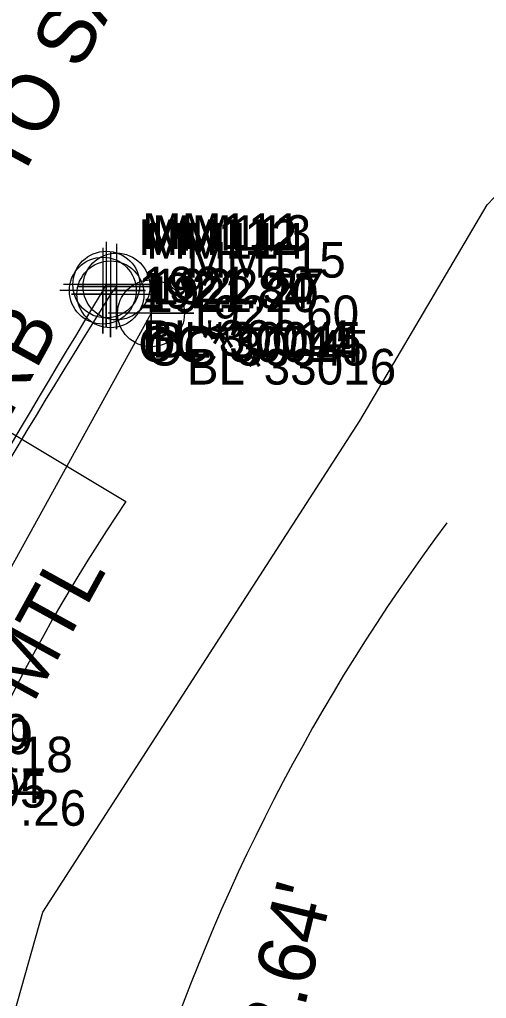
# Model space of a CAD drawing. Extents: x 1004514 to 1005247, y 553695 to 554706.
# Drawn here: x 1005068.7 to 1005101.4, y 554190.9 to 554259.6 of the extents above; entities that cross this region are included whole.
import ezdxf

# ---------------------------------------------------------------- set-up
doc = ezdxf.new("R2010")
doc.units = 0
for name, color, linetype in [('Exist Guardrail', 7, 'Continuous'), ('Exist Guardrail Cogo Comment', 7, 'Continuous'), ('Exist Guardrail Cogo Elevation', 7, 'Continuous'), ('Exist Guardrail Cogo Number', 7, 'Continuous'), ('Exist Guardrail Cogo Point CELL', 7, 'Continuous'), ('Exist Guardrail Text', 7, 'Continuous'), ('Exist Right of Way Line', 7, 'Continuous'), ('Exist Roads Curbs', 7, 'Continuous'), ('Exist Roads Curbs Cogo Comment', 7, 'Continuous'), ('Exist Roads Curbs Cogo Elevation', 7, 'Continuous'), ('Exist Roads Curbs Cogo Number', 7, 'Continuous'), ('Exist Roads Curbs Cogo Point CELL', 7, 'Continuous'), ('Exist Roads Curbs Text', 7, 'Continuous'), ('Exist Roads EOP', 7, 'Continuous'), ('Exist Roads EOP Cogo Comment', 7, 'Continuous'), ('Exist Roads EOP Cogo Elevation', 7, 'Continuous'), ('Exist Roads EOP Cogo Number', 7, 'Continuous'), ('Exist Roads EOP Cogo Point CELL', 7, 'Continuous'), ('Exist Roads EOP Text', 7, 'Continuous'), ('Exist Structure Minor Pipes CMP 30 Inch Invert', 7, 'Continuous'), ('Exist Vegetation Woods Line', 7, 'Continuous'), ('Old_Level_3', 7, 'Continuous')]:
    doc.layers.add(name, color=color, linetype=linetype)

msp = doc.modelspace()

# ---------------------------------------------------------------- linework, layer by layer
at = {"layer": 'Exist Guardrail'}
msp.add_lwpolyline([(1005077.879, 554238.993), (1005058.749, 554204.287), (1005049.992, 554175.596), (1005045.293, 554142.756), (1005044.111, 554102.438), (1005045.04, 554055.452), (1005045.63, 554011.474), (1005045.274, 553965.154), (1005039.583, 553916.738), (1005028.889, 553873.019)], dxfattribs=at)
at = {"layer": 'Exist Guardrail Cogo Point CELL'}
msp.add_lwpolyline([(1005077.879, 554241.993), (1005077.879, 554235.993), (1005077.879, 554238.993), (1005080.879, 554238.993), (1005074.879, 554238.993)], dxfattribs=at)
msp.add_circle((1005077.879, 554238.993), 2.344, dxfattribs=at)
at = {"layer": 'Exist Right of Way Line'}
msp.add_arc((1005209.198, 554141.741), 138, 143.26447, 181.15854, dxfattribs=at)
at = {"layer": 'Exist Roads Curbs'}
msp.add_line((1005075.456, 554240.876), (1005075.03, 554240.325), dxfattribs=at)
msp.add_spline([(1005075.03, 554240.325), (1005055.961, 554205.561), (1005046.997, 554176.639), (1005041.862, 554143.203), (1005041.439, 554133.575)], degree=3, dxfattribs=at)
at = {"layer": 'Exist Roads Curbs Cogo Point CELL'}
for points in [[(1005075.03, 554243.325), (1005075.03, 554237.325), (1005075.03, 554240.325), (1005072.3, 554240.325), (1005078.03, 554240.325)], [(1005075.456, 554243.876), (1005075.456, 554237.876), (1005075.456, 554240.876), (1005072.726, 554240.876), (1005078.456, 554240.876)]]:
    msp.add_lwpolyline(points, dxfattribs=at)
for centre in [(1005075.03, 554240.325), (1005075.456, 554240.876)]:
    msp.add_circle(centre, 2.344, dxfattribs=at)
at = {"layer": 'Exist Roads EOP'}
msp.add_line((1005074.741, 554241.007), (1005074.494, 554240.581), dxfattribs=at)
msp.add_spline([(1005074.494, 554240.581), (1005055.678, 554205.88), (1005046.35, 554176.623), (1005041.386, 554143.248), (1005040.93, 554132.857)], degree=3, dxfattribs=at)
at = {"layer": 'Exist Roads EOP Cogo Point CELL'}
for points in [[(1005074.741, 554244.007), (1005074.741, 554238.007), (1005074.741, 554241.007), (1005077.741, 554241.007), (1005071.741, 554241.007)], [(1005074.494, 554243.581), (1005074.494, 554237.581), (1005074.494, 554240.581), (1005077.494, 554240.581), (1005071.494, 554240.581)]]:
    msp.add_lwpolyline(points, dxfattribs=at)
for centre in [(1005074.741, 554241.007), (1005074.494, 554240.581)]:
    msp.add_circle(centre, 2.344, dxfattribs=at)
at = {"layer": 'Exist Vegetation Woods Line'}
msp.add_lwpolyline([(1005043.245, 553870.571), (1005060.795, 553939.084), (1005067.553, 553999.387), (1005060.697, 554075.478), (1005056.834, 554134.404), (1005061.711, 554166.622), (1005070.29, 554196.972), (1005092.518, 554231.451), (1005101.443, 554246.608), (1005128.922, 554275.434)], dxfattribs=at)
at = {"layer": 'Old_Level_3'}
msp.add_line((1004974.392, 554286.954), (1005076.106, 554225.778), dxfattribs=at)
msp.add_arc((1005179.657, 554155.763), 125, 145.93577, 181.58005, dxfattribs=at)

# ---------------------------------------------------------------- texts
at = {"layer": 'Exist Guardrail Cogo Comment'}
msp.add_text('BL*33016', height=2.5, dxfattribs=at).set_placement((1005080.379, 554233.993))
at = {"layer": 'Exist Guardrail Cogo Elevation'}
for s, p in [('1921.60', (1005080.379, 554237.743)), ('1917.26', (1005061.249, 554203.037))]:
    msp.add_text(s, height=2.5, dxfattribs=at).set_placement(p)
at = {"layer": 'Exist Guardrail Cogo Number'}
for s, p in [('MM115', (1005080.379, 554241.493)), ('MM118', (1005061.249, 554206.787))]:
    msp.add_text(s, height=2.5, dxfattribs=at).set_placement(p)
at = {"layer": 'Exist Guardrail Text'}
msp.add_text('MTL', height=4, rotation=61.1368, dxfattribs=at).set_placement((1005069.61, 554211.561))
at = {"layer": 'Exist Roads Curbs Cogo Comment'}
for s, p in [('OC*30045', (1005077.53, 554235.325)), ('BL*30045', (1005077.956, 554235.876))]:
    msp.add_text(s, height=2.5, dxfattribs=at).set_placement(p)
at = {"layer": 'Exist Roads Curbs Cogo Elevation'}
for s, p in [('1922.27', (1005077.956, 554239.626)), ('1922.20', (1005077.53, 554239.075)), ('1918.05', (1005058.461, 554204.311))]:
    msp.add_text(s, height=2.5, dxfattribs=at).set_placement(p)
at = {"layer": 'Exist Roads Curbs Cogo Number'}
for s, p in [('MM113', (1005077.956, 554243.376)), ('MM114', (1005077.53, 554242.825)), ('MM119', (1005058.461, 554208.061))]:
    msp.add_text(s, height=2.5, dxfattribs=at).set_placement(p)
at = {"layer": 'Exist Roads Curbs Text'}
msp.add_text('6" BST CURB', height=4, rotation=61.25355, dxfattribs=at).set_placement((1005055.455, 554208.797))
at = {"layer": 'Exist Roads EOP Cogo Comment'}
for s, p in [('BL*30014', (1005077.241, 554236.007)), ('OC*30014', (1005076.994, 554235.581))]:
    msp.add_text(s, height=2.5, dxfattribs=at).set_placement(p)
at = {"layer": 'Exist Roads EOP Cogo Elevation'}
for s, p in [('1921.90', (1005077.241, 554239.757)), ('1921.84', (1005076.994, 554239.331)), ('1917.74', (1005058.178, 554204.63))]:
    msp.add_text(s, height=2.5, dxfattribs=at).set_placement(p)
at = {"layer": 'Exist Roads EOP Cogo Number'}
for s, p in [('MM112', (1005076.994, 554243.081)), ('MM111', (1005077.241, 554243.507)), ('MM120', (1005058.178, 554208.38))]:
    msp.add_text(s, height=2.5, dxfattribs=at).set_placement(p)
at = {"layer": 'Exist Roads EOP Text'}
msp.add_text('TO SALUDA', height=4, rotation=61.53119, dxfattribs=at).set_placement((1005068.629, 554248.128))
at = {"layer": 'Exist Structure Minor Pipes CMP 30 Inch Invert'}
msp.add_text("INV=1903.64'", height=4, rotation=76.1869, dxfattribs=at).set_placement((1005082.911, 554166.949))

doc.saveas('drawing.dxf')
